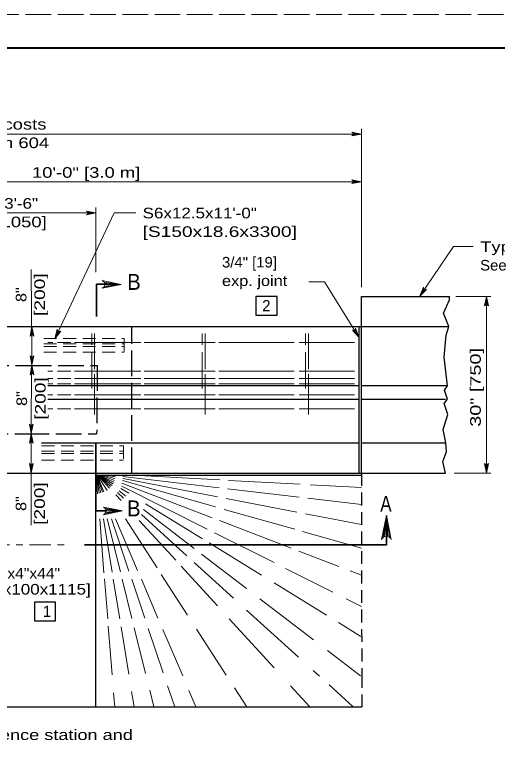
# Model space of a CAD drawing. Extents: x -1431.2 to -1397.2, y -1045.1 to -1001.1.
# Drawn here: x -1416.18 to -1408.95, y -1011.99 to -1001.08 of the extents above; entities that cross this region are included whole.
import ezdxf
from ezdxf.enums import TextEntityAlignment as Align

# ---------------------------------------------------------------- set-up
doc = ezdxf.new("R2010")
doc.units = 0
doc.header["$LTSCALE"] = 0.064
for name, pattern in [('DOT_DASHED', [7.7, 5, -1.2, 0.3, -1.2]), ('LONG_DASHED', [7.5, 6, -1.5]), ('MEDIUM_DASHED', [4.5, 3, -1.5])]:
    doc.linetypes.add(name, pattern=pattern)
doc.layers.add('1', color=7, linetype='Continuous', lineweight=13)

msp = doc.modelspace()

# ---------------------------------------------------------------- linework, layer by layer
at = {"layer": '1', "lineweight": 25}
for p, q in [((-1429.24575, -1001.57983), (-1397.74575, -1001.57983)), ((-1410.98825, -1007.95217), (-1410.98825, -1005.30383)), ((-1410.98825, -1005.30383), (-1409.67133, -1005.30383)), ((-1416.00942, -1005.75617), (-1414.95508, -1005.75617)), ((-1411.0205, -1007.95217), (-1411.0205, -1005.75617)), ((-1415.685, -1006.64083), (-1411.0205, -1006.64083)), ((-1410.98825, -1006.64083), (-1409.69992, -1006.64083)), ((-1415.685, -1006.84225), (-1411.0205, -1006.84225)), ((-1410.98825, -1006.84225), (-1409.7285, -1006.84225)), ((-1415.77883, -1007.49992), (-1411.0205, -1007.49992)), ((-1410.98825, -1007.49992), (-1409.72375, -1007.49992)), ((-1417.52008, -1007.95217), (-1416.00558, -1007.95217)), ((-1414.96492, -1007.98392), (-1410.98817, -1007.98392)), ((-1414.96492, -1011.455), (-1414.96492, -1008.517)), ((-1426.97542, -1011.455), (-1410.98333, -1011.455))]:
    msp.add_line(p, q, dxfattribs=at)
at = {"layer": '1'}
for p, q in [((-1410.9895, -1005.16692), (-1410.9895, -1002.794)), ((-1426.97675, -1002.87033), (-1410.9895, -1002.87033)), ((-1411.12042, -1002.85033), (-1410.9895, -1002.87033)), ((-1411.11883, -1002.88842), (-1410.9895, -1002.87033)), ((-1411.11542, -1002.85867), (-1410.9895, -1002.87033)), ((-1411.1145, -1002.87942), (-1410.9895, -1002.87033)), ((-1411.11317, -1002.87033), (-1410.9895, -1002.87033)), ((-1411.12042, -1003.56475), (-1410.9895, -1003.58475)), ((-1411.11542, -1003.57317), (-1410.9895, -1003.58475)), ((-1426.97675, -1003.58475), (-1410.9895, -1003.58475)), ((-1411.11883, -1003.60283), (-1410.9895, -1003.58475)), ((-1411.1145, -1003.59392), (-1410.9895, -1003.58475)), ((-1411.11317, -1003.58475), (-1410.9895, -1003.58475)), ((-1414.96492, -1004.93992), (-1414.96492, -1003.97283)), ((-1414.96492, -1004.05217), (-1422.96592, -1004.05217)), ((-1415.09583, -1004.03217), (-1414.96492, -1004.05217)), ((-1415.09433, -1004.07025), (-1414.96492, -1004.05217)), ((-1415.09083, -1004.04058), (-1414.96492, -1004.05217)), ((-1415.08992, -1004.06133), (-1414.96492, -1004.05217)), ((-1415.08858, -1004.05217), (-1414.96492, -1004.05217)), ((-1415.92392, -1006.184), (-1415.93375, -1004.90083)), ((-1414.84508, -1005.08817), (-1414.58633, -1005.12433)), ((-1414.83633, -1005.10608), (-1414.58633, -1005.12433)), ((-1414.84808, -1005.16433), (-1414.58633, -1005.12433)), ((-1414.83817, -1005.14758), (-1414.58633, -1005.12433)), ((-1414.83367, -1005.12433), (-1414.58633, -1005.12433)), ((-1410.05742, -1005.18242), (-1410.11517, -1005.29958)), ((-1410.0525, -1005.19108), (-1410.11517, -1005.29958)), ((-1410.04567, -1005.19733), (-1410.11517, -1005.29958)), ((-1410.03483, -1005.202), (-1410.11517, -1005.29958)), ((-1410.02508, -1005.20258), (-1410.11517, -1005.29958)), ((-1409.57192, -1005.30383), (-1409.04808, -1005.30383)), ((-1409.13475, -1005.43475), (-1409.11475, -1005.30383)), ((-1409.12642, -1005.42983), (-1409.11475, -1005.30383)), ((-1409.11475, -1005.30383), (-1409.11475, -1007.95217)), ((-1409.11475, -1005.4275), (-1409.11475, -1005.30383)), ((-1409.10567, -1005.42883), (-1409.11475, -1005.30383)), ((-1409.09667, -1005.43325), (-1409.11475, -1005.30383)), ((-1415.944, -1005.887), (-1415.92392, -1005.75617)), ((-1415.93558, -1005.88208), (-1415.92392, -1005.75617)), ((-1415.92392, -1005.87983), (-1415.92392, -1005.75617)), ((-1415.91483, -1005.88117), (-1415.92392, -1005.75617)), ((-1415.90583, -1005.8855), (-1415.92392, -1005.75617)), ((-1415.54183, -1005.81333), (-1415.58283, -1005.93733)), ((-1415.53575, -1005.82125), (-1415.58283, -1005.93733)), ((-1415.52808, -1005.82642), (-1415.58283, -1005.93733)), ((-1415.507, -1005.82883), (-1415.58283, -1005.93733)), ((-1415.51667, -1005.82958), (-1415.58283, -1005.93733)), ((-1415.02725, -1005.85733), (-1415.02725, -1006.02692)), ((-1414.98492, -1005.85733), (-1414.98492, -1006.39358)), ((-1413.37308, -1005.85733), (-1413.37308, -1006.02692)), ((-1413.33075, -1005.85733), (-1413.33075, -1006.39358)), ((-1411.82383, -1005.85733), (-1411.82383, -1006.02692)), ((-1411.7815, -1005.85733), (-1411.7815, -1006.39358)), ((-1411.10717, -1005.81475), (-1411.02758, -1005.91342)), ((-1411.09758, -1005.81392), (-1411.02758, -1005.91342)), ((-1411.08933, -1005.8105), (-1411.02758, -1005.91342)), ((-1411.08075, -1005.80283), (-1411.02758, -1005.91342)), ((-1411.07625, -1005.7945), (-1411.02758, -1005.91342)), ((-1415.685, -1005.99167), (-1415.61133, -1005.99167)), ((-1415.54258, -1005.99167), (-1415.34125, -1005.99167)), ((-1415.28858, -1005.99167), (-1414.29458, -1005.99167)), ((-1414.24192, -1005.99167), (-1413.18158, -1005.99167)), ((-1413.12333, -1005.99167), (-1411.99608, -1005.99167)), ((-1411.92092, -1005.99167), (-1411.09442, -1005.99167)), ((-1415.02725, -1006.139), (-1415.02725, -1006.68142)), ((-1413.37308, -1006.139), (-1413.37308, -1006.68142)), ((-1411.82383, -1006.139), (-1411.82383, -1006.68142)), ((-1415.94208, -1006.20658), (-1415.92392, -1006.33592)), ((-1415.93308, -1006.21092), (-1415.92392, -1006.33592)), ((-1415.90392, -1006.205), (-1415.92392, -1006.33592)), ((-1415.91233, -1006.21), (-1415.92392, -1006.33592)), ((-1415.92392, -1006.21225), (-1415.92392, -1006.33592)), ((-1415.944, -1006.46683), (-1415.92392, -1006.33592)), ((-1415.93558, -1006.46183), (-1415.92392, -1006.33592)), ((-1415.92392, -1006.45958), (-1415.92392, -1006.33592)), ((-1415.91483, -1006.46092), (-1415.92392, -1006.33592)), ((-1415.90583, -1006.46525), (-1415.92392, -1006.33592)), ((-1415.685, -1006.42175), (-1415.61133, -1006.42175)), ((-1415.54258, -1006.42175), (-1415.34125, -1006.42175)), ((-1415.28858, -1006.42175), (-1414.29458, -1006.42175)), ((-1414.98492, -1006.46925), (-1414.98492, -1007.07475)), ((-1414.24192, -1006.42175), (-1413.18158, -1006.42175)), ((-1413.33075, -1006.46925), (-1413.33075, -1007.07475)), ((-1413.12333, -1006.42175), (-1411.99608, -1006.42175)), ((-1411.92092, -1006.42175), (-1411.09442, -1006.42175)), ((-1411.7815, -1006.46925), (-1411.7815, -1007.07475)), ((-1415.685, -1006.53208), (-1415.61133, -1006.53208)), ((-1415.685, -1006.612), (-1415.61133, -1006.612)), ((-1415.54258, -1006.53208), (-1415.34125, -1006.53208)), ((-1415.54258, -1006.612), (-1415.34125, -1006.612)), ((-1415.28858, -1006.53208), (-1414.29458, -1006.53208)), ((-1415.28858, -1006.612), (-1414.29458, -1006.612)), ((-1414.24192, -1006.53208), (-1413.18158, -1006.53208)), ((-1414.24192, -1006.612), (-1413.18158, -1006.612)), ((-1413.12333, -1006.53208), (-1411.99608, -1006.53208)), ((-1413.12333, -1006.612), (-1411.99608, -1006.612)), ((-1411.92092, -1006.53208), (-1411.09442, -1006.53208)), ((-1411.92092, -1006.612), (-1411.09442, -1006.612)), ((-1415.685, -1006.77592), (-1415.61133, -1006.77592)), ((-1415.54258, -1006.77592), (-1415.34125, -1006.77592)), ((-1415.28858, -1006.77592), (-1414.29458, -1006.77592)), ((-1414.24192, -1006.77592), (-1413.18158, -1006.77592)), ((-1413.12333, -1006.77592), (-1411.99608, -1006.77592)), ((-1411.92092, -1006.77592), (-1411.09442, -1006.77592)), ((-1415.685, -1006.98883), (-1415.61133, -1006.98883)), ((-1415.54258, -1006.98883), (-1415.34125, -1006.98883)), ((-1415.28858, -1006.98883), (-1414.29458, -1006.98883)), ((-1414.24192, -1006.98883), (-1413.18158, -1006.98883)), ((-1413.12333, -1006.98883), (-1411.99608, -1006.98883)), ((-1411.92092, -1006.98883), (-1411.09442, -1006.98883)), ((-1415.95183, -1007.23), (-1415.93375, -1007.35933)), ((-1415.94292, -1007.23442), (-1415.93375, -1007.35933)), ((-1415.91375, -1007.2285), (-1415.93375, -1007.35933)), ((-1415.92217, -1007.23342), (-1415.93375, -1007.35933)), ((-1415.93375, -1007.23575), (-1415.93375, -1007.35933)), ((-1415.95375, -1007.49025), (-1415.93375, -1007.35933)), ((-1415.94542, -1007.48533), (-1415.93375, -1007.35933)), ((-1415.93375, -1007.483), (-1415.93375, -1007.35933)), ((-1415.92467, -1007.48433), (-1415.93375, -1007.35933)), ((-1415.91567, -1007.48875), (-1415.93375, -1007.35933)), ((-1415.93375, -1007.49992), (-1415.93375, -1008.7325)), ((-1411.0205, -1007.49992), (-1415.77883, -1007.49992)), ((-1414.96492, -1007.49992), (-1414.96492, -1007.95217)), ((-1415.95183, -1007.82283), (-1415.93375, -1007.95217)), ((-1415.94292, -1007.82717), (-1415.93375, -1007.95217)), ((-1415.91375, -1007.82133), (-1415.93375, -1007.95217)), ((-1415.92217, -1007.82625), (-1415.93375, -1007.95217)), ((-1415.93375, -1007.8285), (-1415.93375, -1007.95217)), ((-1409.13292, -1007.82283), (-1409.11475, -1007.95217)), ((-1409.12392, -1007.82717), (-1409.11475, -1007.95217)), ((-1409.09475, -1007.82133), (-1409.11475, -1007.95217)), ((-1409.10317, -1007.82625), (-1409.11475, -1007.95217)), ((-1409.11475, -1007.8285), (-1409.11475, -1007.95217)), ((-1414.96492, -1007.95217), (-1414.96425, -1007.95625)), ((-1414.96492, -1007.95217), (-1414.96433, -1007.95483)), ((-1414.96492, -1007.95217), (-1414.96433, -1007.95408)), ((-1414.96492, -1007.95217), (-1414.96433, -1007.95367)), ((-1414.96492, -1007.95217), (-1414.96433, -1007.95317)), ((-1414.96492, -1007.95217), (-1414.96433, -1007.95275)), ((-1414.96492, -1007.95217), (-1414.96433, -1007.95267)), ((-1414.96492, -1007.95217), (-1414.96433, -1007.95258)), ((-1414.96492, -1007.95217), (-1414.96433, -1007.9525)), ((-1414.96492, -1007.95217), (-1414.96433, -1007.95242)), ((-1414.96492, -1007.95217), (-1414.96433, -1007.95225)), ((-1414.96492, -1007.95217), (-1414.96433, -1007.95225)), ((-1414.96492, -1007.95217), (-1414.96425, -1007.96083)), ((-1414.96492, -1007.95217), (-1414.96433, -1007.95292)), ((-1414.96492, -1007.95217), (-1414.96433, -1007.95233)), ((-1414.96492, -1007.95217), (-1414.96433, -1007.95233)), ((-1414.96208, -1007.988), (-1414.94017, -1008.26017)), ((-1414.95908, -1007.98792), (-1414.91608, -1008.2525)), ((-1414.95608, -1007.98792), (-1414.89208, -1008.24675)), ((-1414.95292, -1007.98783), (-1414.86842, -1008.23892)), ((-1414.94967, -1007.98783), (-1414.84625, -1008.22983)), ((-1414.942, -1007.98775), (-1414.79833, -1008.2105)), ((-1414.9325, -1007.98767), (-1414.76142, -1008.17467)), ((-1414.926, -1007.98758), (-1414.74575, -1008.1515)), ((-1414.91883, -1007.9875), (-1414.72425, -1008.13658)), ((-1414.90783, -1007.98742), (-1414.70825, -1008.11042)), ((-1414.89508, -1007.98725), (-1414.69617, -1008.08717)), ((-1414.87417, -1007.98708), (-1414.68525, -1008.05958)), ((-1414.8425, -1007.98675), (-1414.68133, -1008.03217)), ((-1414.7895, -1007.98617), (-1414.67342, -1008.00867)), ((-1414.68558, -1007.98508), (-1414.66817, -1007.98717)), ((-1414.56242, -1007.99958), (-1413.1185, -1008.16975)), ((-1414.55925, -1008.03075), (-1413.14658, -1008.30433)), ((-1414.42025, -1007.98167), (-1413.10717, -1008.05275)), ((-1409.6005, -1007.95217), (-1409.04808, -1007.95217)), ((-1414.57908, -1008.146), (-1413.29792, -1008.78975)), ((-1414.57625, -1008.10142), (-1413.22517, -1008.62033)), ((-1414.5675, -1008.06425), (-1413.17308, -1008.4575)), ((-1412.97983, -1008.05967), (-1411.90383, -1008.11783)), ((-1411.75558, -1008.12592), (-1410.988, -1008.1675)), ((-1414.6445, -1008.24333), (-1414.55192, -1008.3275)), ((-1414.61942, -1008.21683), (-1414.51767, -1008.29483)), ((-1414.59325, -1008.18117), (-1414.475, -1008.25408)), ((-1412.99367, -1008.1845), (-1411.92267, -1008.31067)), ((-1414.66992, -1008.27475), (-1414.58908, -1008.363)), ((-1413.01575, -1008.32975), (-1411.95808, -1008.53458)), ((-1411.78967, -1008.32633), (-1410.98758, -1008.42092)), ((-1414.82692, -1008.48075), (-1414.56825, -1008.517)), ((-1414.2225, -1008.40958), (-1413.36992, -1008.935)), ((-1414.83, -1008.557), (-1414.56825, -1008.517)), ((-1414.82008, -1008.54025), (-1414.56825, -1008.517)), ((-1414.81817, -1008.49867), (-1414.56825, -1008.517)), ((-1414.8155, -1008.517), (-1414.56825, -1008.517)), ((-1414.28092, -1008.57383), (-1413.60225, -1009.19075)), ((-1414.25533, -1008.49575), (-1413.49358, -1009.07933)), ((-1413.0425, -1008.49442), (-1411.98667, -1008.79217)), ((-1411.82442, -1008.5605), (-1410.98717, -1008.72267)), ((-1410.66425, -1008.91608), (-1410.61425, -1008.58883)), ((-1410.64333, -1008.90367), (-1410.61425, -1008.58883)), ((-1410.61425, -1008.898), (-1410.61425, -1008.58883)), ((-1410.59142, -1008.90133), (-1410.61425, -1008.58883)), ((-1410.569, -1008.91225), (-1410.61425, -1008.58883)), ((-1414.90983, -1008.63808), (-1414.84525, -1009.44342)), ((-1414.85333, -1008.63767), (-1414.72333, -1009.43625)), ((-1414.79542, -1008.63767), (-1414.59975, -1009.429)), ((-1414.73417, -1008.63767), (-1414.4705, -1009.42067)), ((-1414.67183, -1008.63767), (-1414.34067, -1009.41217)), ((-1414.52517, -1008.63408), (-1414.04867, -1009.37275)), ((-1414.31767, -1008.65967), (-1413.77092, -1009.25717)), ((-1413.11392, -1008.663), (-1412.0405, -1009.07525)), ((-1413.18717, -1008.84533), (-1412.297, -1009.29258)), ((-1411.8725, -1008.82433), (-1410.98667, -1009.07417)), ((-1413.26933, -1008.997), (-1412.48775, -1009.4785)), ((-1411.92658, -1009.11892), (-1411.32508, -1009.34983)), ((-1413.38217, -1009.16458), (-1412.70817, -1009.68083)), ((-1413.68775, -1009.34808), (-1413.1445, -1009.94167)), ((-1413.49392, -1009.28908), (-1412.90408, -1009.82558)), ((-1413.98667, -1009.46892), (-1413.59158, -1010.08142)), ((-1412.12575, -1009.37867), (-1411.41667, -1009.73492)), ((-1411.15725, -1009.41433), (-1410.98608, -1009.48008)), ((-1414.83775, -1009.53642), (-1414.78958, -1010.13683)), ((-1414.70667, -1009.53883), (-1414.60983, -1010.13358)), ((-1414.572, -1009.54133), (-1414.42642, -1010.13033)), ((-1414.42983, -1009.54142), (-1414.23275, -1010.12683)), ((-1414.28533, -1009.54142), (-1414.03692, -1010.12242)), ((-1412.29533, -1009.59708), (-1411.51158, -1010.07992)), ((-1412.50867, -1009.83367), (-1411.70592, -1010.44858)), ((-1411.21792, -1009.83475), (-1410.98542, -1009.95158)), ((-1412.7095, -1010.0025), (-1411.93042, -1010.71117)), ((-1412.96767, -1010.135), (-1412.29442, -1010.87083)), ((-1411.33317, -1010.18992), (-1410.9965, -1010.39725)), ((-1414.78092, -1010.24492), (-1414.7225, -1010.97217)), ((-1414.58975, -1010.25692), (-1414.47425, -1010.9665)), ((-1414.39233, -1010.26825), (-1414.22283, -1010.95383)), ((-1414.18108, -1010.28033), (-1413.95842, -1010.94158)), ((-1413.96417, -1010.29258), (-1413.66608, -1010.98958)), ((-1413.45875, -1010.28733), (-1413.01242, -1010.97933)), ((-1411.49517, -1010.61008), (-1411.00017, -1010.98925)), ((-1411.71033, -1010.91125), (-1411.61725, -1010.99592)), ((-1414.16067, -1011.20533), (-1414.09892, -1011.455)), ((-1413.89125, -1011.141), (-1413.7855, -1011.455)), ((-1413.57158, -1011.21058), (-1413.46708, -1011.455)), ((-1412.88925, -1011.17008), (-1412.7055, -1011.455)), ((-1412.05142, -1011.1365), (-1411.76, -1011.455)), ((-1411.47333, -1011.1255), (-1411.11075, -1011.455)), ((-1414.70067, -1011.24417), (-1414.68375, -1011.455)), ((-1414.43225, -1011.22458), (-1414.39483, -1011.455))]:
    msp.add_line(p, q, dxfattribs=at)
at = {"layer": '1', "lineweight": 35}
for p, q in [((-1414.80358, -1005.11975), (-1414.95508, -1005.11975)), ((-1414.95508, -1005.60267), (-1414.95508, -1005.11975)), ((-1414.96492, -1007.49992), (-1414.96492, -1008.517)), ((-1414.80358, -1008.517), (-1414.96492, -1008.517)), ((-1410.61425, -1008.58883), (-1410.61425, -1009.0255)), ((-1415.13658, -1009.0255), (-1410.61425, -1009.0255))]:
    msp.add_line(p, q, dxfattribs=at)
at = {"layer": '1', "linetype": 'LONG_DASHED', "lineweight": 25}
for p, q in [((-1414.42775, -1007.95217), (-1414.42775, -1005.75617)), ((-1414.94533, -1006.33642), (-1414.95508, -1007.36058))]:
    msp.add_line(p, q, dxfattribs=at)
at = {"layer": '1', "linetype": 'MEDIUM_DASHED'}
for p, q in [((-1415.74783, -1005.93558), (-1414.54258, -1005.93558)), ((-1414.54258, -1005.93558), (-1414.54258, -1006.14133)), ((-1415.74783, -1006.01425), (-1414.54258, -1006.01425)), ((-1415.74783, -1006.056), (-1414.54258, -1006.056)), ((-1415.74783, -1006.14133), (-1414.54258, -1006.14133)), ((-1415.77883, -1007.5445), (-1414.55242, -1007.5445)), ((-1414.55242, -1007.5445), (-1414.55242, -1007.75642)), ((-1415.77883, -1007.6225), (-1414.55242, -1007.6225)), ((-1415.77883, -1007.65542), (-1414.55242, -1007.65542)), ((-1415.77883, -1007.75642), (-1414.55242, -1007.75642))]:
    msp.add_line(p, q, dxfattribs=at)
at = {"layer": '1', "linetype": 'DOT_DASHED'}
msp.add_line((-1420.92175, -1009.0255), (-1415.34425, -1009.0255), dxfattribs=at)
at = {"layer": '1', "linetype": 'LONG_DASHED'}
msp.add_lwpolyline([(-1431.24575, -1023.07983), (-1397.24575, -1023.07983), (-1397.24575, -1001.07983), (-1431.24575, -1001.07983)], close=True, dxfattribs=at)
at = {"layer": '1', "lineweight": 40}
msp.add_lwpolyline([(-1429.24575, -1001.57983), (-1397.74575, -1001.57983), (-1397.74575, -1022.57983), (-1429.24575, -1022.57983)], close=True, dxfattribs=at)
at = {"layer": '1'}
for points in [[(-1411.13242, -1002.84175), (-1410.9895, -1002.87033), (-1411.13242, -1002.89892)], [(-1411.13242, -1003.55617), (-1410.9895, -1003.58475), (-1411.13242, -1003.61333)], [(-1415.58283, -1005.93733), (-1414.6935, -1004.05308), (-1414.368, -1004.05308)], [(-1415.10783, -1004.02358), (-1414.96492, -1004.05217), (-1415.10783, -1004.08075)], [(-1410.11517, -1005.29958), (-1409.61025, -1004.55792), (-1409.31483, -1004.55792)], [(-1414.87208, -1005.1815), (-1414.58633, -1005.12433), (-1414.87208, -1005.06717)], [(-1411.02733, -1005.914), (-1411.54183, -1005.08733), (-1411.77525, -1005.08733)], [(-1410.01125, -1005.1975), (-1410.11517, -1005.29958), (-1410.0585, -1005.16533)], [(-1409.14333, -1005.44675), (-1409.11475, -1005.30383), (-1409.08617, -1005.44675)], [(-1415.9525, -1005.899), (-1415.92392, -1005.75617), (-1415.89542, -1005.899)], [(-1415.494, -1005.82183), (-1415.58283, -1005.93733), (-1415.54525, -1005.79658)], [(-1411.07508, -1005.78025), (-1411.02758, -1005.91342), (-1411.12267, -1005.80875)], [(-1415.89542, -1006.193), (-1415.92392, -1006.33592), (-1415.9525, -1006.193)], [(-1415.92392, -1006.184), (-1415.93375, -1007.04942), (-1415.93375, -1007.49992)], [(-1415.9525, -1006.47883), (-1415.92392, -1006.33592), (-1415.89542, -1006.47883)], [(-1415.90517, -1007.2165), (-1415.93375, -1007.35933), (-1415.96233, -1007.2165)], [(-1415.96233, -1007.50225), (-1415.93375, -1007.35933), (-1415.90517, -1007.50225)], [(-1415.90517, -1007.80933), (-1415.93375, -1007.95217), (-1415.96233, -1007.80933)], [(-1409.08617, -1007.80933), (-1409.11475, -1007.95217), (-1409.14333, -1007.80933)], [(-1414.854, -1008.57408), (-1414.56825, -1008.517), (-1414.854, -1008.45983)], [(-1410.68567, -1008.94608), (-1410.61425, -1008.58883), (-1410.54283, -1008.94608)]]:
    msp.add_lwpolyline(points, dxfattribs=at)
at = {"layer": '1', "lineweight": 25}
for points in [[(-1412.5695, -1005.30567), (-1412.5695, -1005.58375), (-1412.25233, -1005.58375), (-1412.25233, -1005.30567)], [(-1415.88808, -1009.8865), (-1415.88808, -1010.16433), (-1415.57083, -1010.16433), (-1415.57083, -1009.8865)]]:
    msp.add_lwpolyline(points, close=True, dxfattribs=at)
for points in [[(-1409.7285, -1007.95217), (-1409.76658, -1007.77617), (-1409.71425, -1007.63325), (-1409.72375, -1007.49992), (-1409.76183, -1007.29808), (-1409.69517, -1007.07475), (-1409.74758, -1006.90942), (-1409.69992, -1006.84233), (-1409.74283, -1006.70833), (-1409.69992, -1006.64092), (-1409.74758, -1006.21242), (-1409.719, -1005.88625), (-1409.68083, -1005.75617), (-1409.75708, -1005.55558), (-1409.67133, -1005.3545), (-1409.67133, -1005.30383)], [(-1427.95475, -1005.75617), (-1426.94317, -1005.75617), (-1409.68083, -1005.75617)], [(-1416.00558, -1007.95217), (-1414.96492, -1007.95217), (-1409.7285, -1007.95217)]]:
    msp.add_lwpolyline(points, dxfattribs=at)
at = {"layer": '1', "linetype": 'LONG_DASHED', "lineweight": 25}
for points in [[(-1422.94908, -1006.33642), (-1416.01508, -1006.33642), (-1414.94533, -1006.33642)], [(-1422.95892, -1007.36058), (-1416.0495, -1007.36058), (-1414.95508, -1007.36058)]]:
    msp.add_lwpolyline(points, dxfattribs=at)
at = {"layer": '1', "linetype": 'MEDIUM_DASHED', "lineweight": 25}
msp.add_lwpolyline([(-1410.98825, -1007.95217), (-1410.984, -1010.97842), (-1410.98333, -1011.455)], dxfattribs=at)
at = {"layer": '1'}
for centre, radius, start, end in [((-1411.14393, -1002.87034), 0.03084, 292.08782, 67.91395), ((-1411.14393, -1003.58479), 0.03084, 292.08782, 67.91395), ((-1415.11937, -1004.05222), 0.03084, 292.08782, 67.91395), ((-1414.8952, -1005.12427), 0.06168, 292.08605, 67.91218), ((-1410.02842, -1005.17188), 0.03084, 167.88661, 303.71274), ((-1409.11476, -1005.45829), 0.03084, 22.08782, 157.91395), ((-1415.51452, -1005.79883), 0.03084, 175.81355, 311.63968), ((-1415.92392, -1005.91058), 0.03084, 22.08782, 157.91395), ((-1415.92399, -1006.18148), 0.03084, 202.08782, 337.91395), ((-1415.92392, -1006.49034), 0.03084, 22.08782, 157.91395), ((-1415.9338, -1007.20494), 0.03084, 202.08782, 337.91395), ((-1415.93374, -1007.5138), 0.03084, 22.08782, 157.91395), ((-1415.9338, -1007.79776), 0.03084, 202.08782, 337.91395), ((-1409.11482, -1007.79776), 0.03084, 202.08782, 337.91395), ((-1414.87707, -1008.5169), 0.06168, 292.08605, 67.91218), ((-1410.61418, -1008.97493), 0.0771, 22.08782, 157.91395)]:
    msp.add_arc(centre, radius, start, end, dxfattribs=at)
msp.add_ellipse((-1411.10467, -1005.78484), major_axis=(0.00853, -0.02869), ratio=0.999895, start_param=5.34910555, end_param=7.71971869, dxfattribs=at)

# ---------------------------------------------------------------- texts
for s, width, p in [('Deduct 20\'-0" [6.0 m] from concrete barrier; All costs', 1.3, (-1418.90437, -1002.80333)), ('for concrete barrier and inlet are included in Item 604', 1.3, (-1418.90442, -1003.08117)), ('3\'-6"', 1.2, (-1416.08675, -1003.989)), ('[1050]', 1.3, (-1416.08675, -1004.26683))]:
    msp.add_text(s, height=0.1588, dxfattribs=dict(at, width=width)).set_placement(p, align=Align.CENTER)
for s, height, width, p in [('10\'-0" [3.0 m]', 0.1588, 1.3, (-1415.924, -1003.52567)), ('S6x12.5x11\'-0"', 0.1588, 1.2, (-1414.26658, -1004.13383)), ('[S150x18.6x3300]', 0.1588, 1.35, (-1414.26658, -1004.41167)), ('Type D barrier.', 0.1588, 1.3, (-1409.20983, -1004.6375)), ('3/4" [19]', 0.1588, 1.05, (-1413.07708, -1004.87008)), ('See', 0.1588, 1.05, (-1409.20983, -1004.91533)), ('B', 0.2382, 0.95, (-1414.4965, -1005.20517)), ('exp. joint', 0.1588, 1.15, (-1413.07708, -1005.14792)), ('B', 0.2382, 0.95, (-1414.49867, -1008.59875)), ('A', 0.2382, 0.8, (-1410.70658, -1008.53067)), ('4 1/2\'x4"x44"', 0.1588, 1.1, (-1416.85708, -1009.53308)), ('[115x100x1115]', 0.1588, 1.2, (-1416.85708, -1009.77125)), ('1', 0.1682, 0.95, (-1415.75825, -1010.10583)), ('Reference station and ', 0.156, 1.3, (-1417.06625, -1011.95083))]:
    msp.add_text(s, height=height, dxfattribs=dict(at, width=width)).set_placement(p)
for s, width, p in [('[200]', 1.35, (-1415.72933, -1005.27675)), ('8"', 1.15, (-1416.00717, -1005.27675)), ('[200]', 1.35, (-1415.71942, -1006.83367)), ('8"', 1.15, (-1415.99725, -1006.83367)), ('[200]', 1.35, (-1415.73092, -1008.40758)), ('8"', 1.15, (-1416.00875, -1008.40758))]:
    msp.add_text(s, height=0.1588, rotation=90, dxfattribs=dict(at, width=width)).set_placement(p, align=Align.CENTER)
msp.add_text('2', height=0.1682, dxfattribs=at).set_placement((-1412.47542, -1005.52675))
at = {"layer": '1', "width": 1.4}
msp.add_text('30" [750]', height=0.1588, rotation=90, dxfattribs=at).set_placement((-1409.2005, -1007.25667))

doc.saveas('drawing.dxf')
